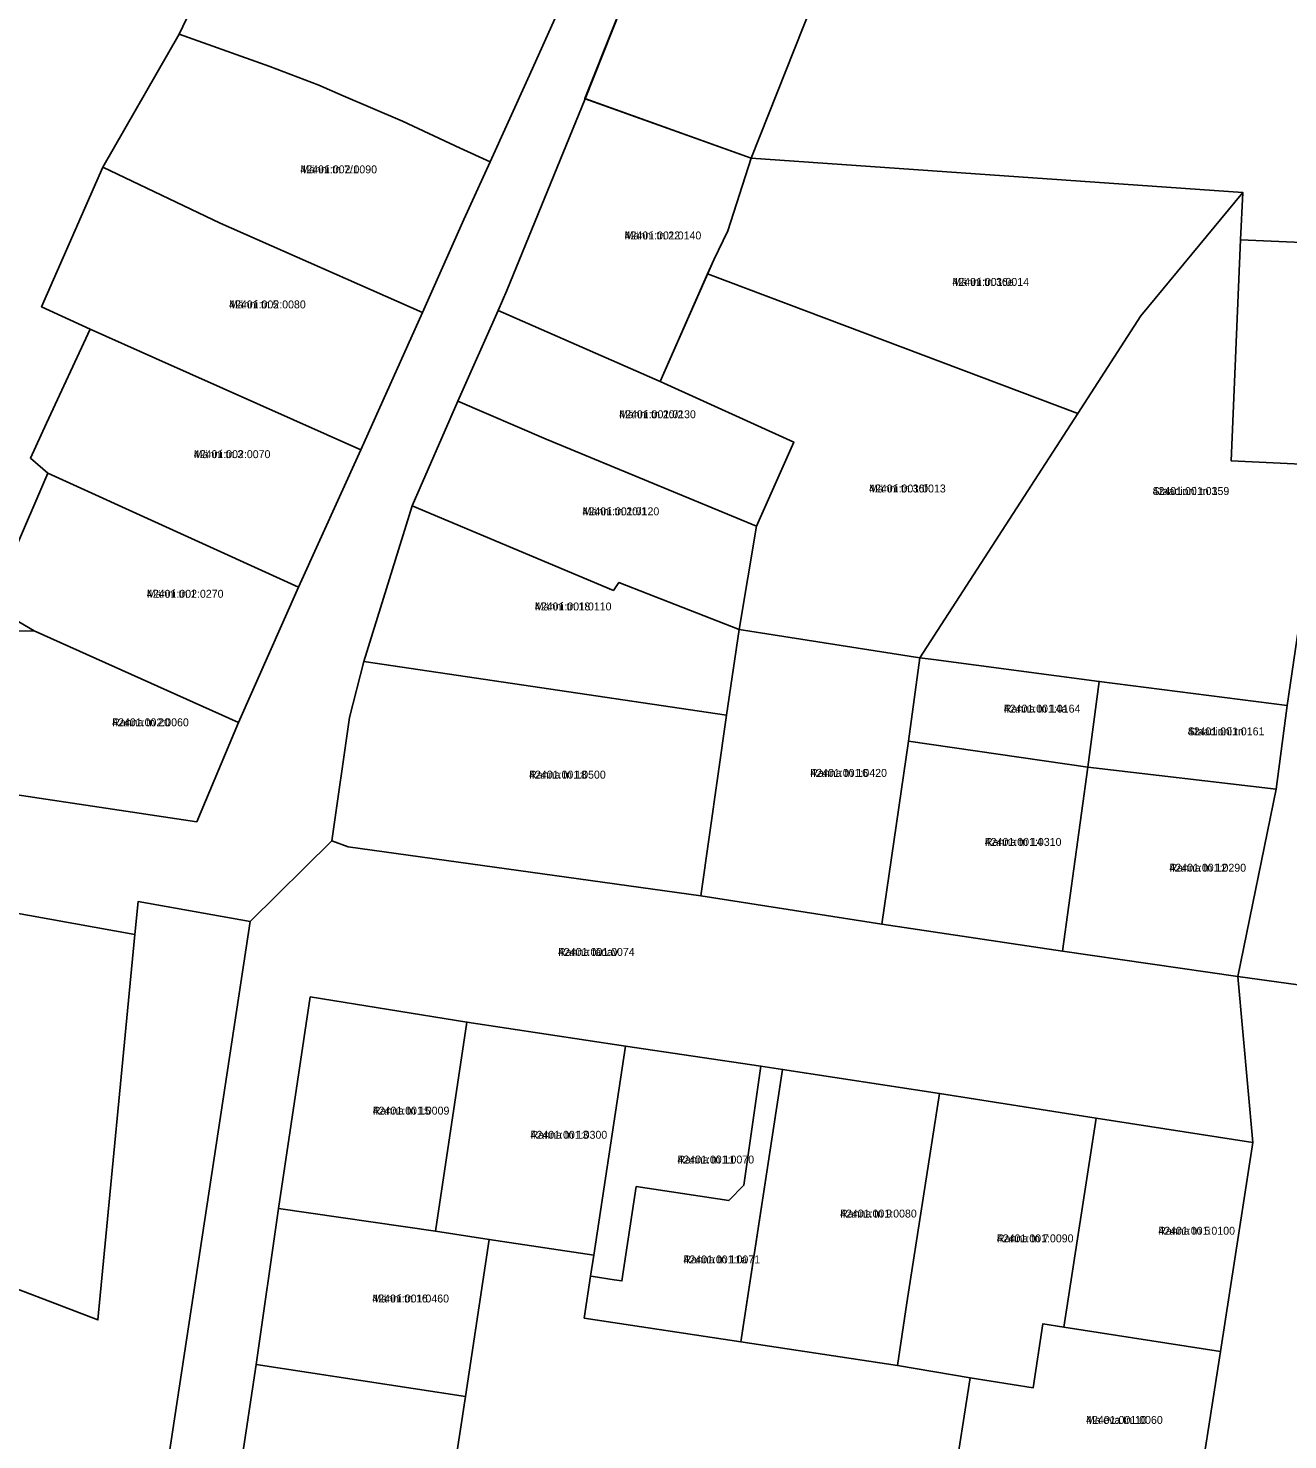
# Model space of a CAD drawing. Extents: x 595979 to 597983, y 6604231 to 6607350.
# Drawn here: x 596786.2 to 597024.3, y 6605469.2 to 6605736 of the extents above; entities that cross this region are included whole.
import ezdxf

# ---------------------------------------------------------------- set-up
doc = ezdxf.new("R2010")
doc.units = 0
for name, color, linetype in [('L_AADRESS', 7, 'Continuous'), ('PIIR', 7, 'Continuous'), ('TUNNUS', 7, 'Continuous')]:
    doc.layers.add(name, color=color, linetype=linetype)

msp = doc.modelspace()

# ---------------------------------------------------------------- linework, layer by layer
at = {"layer": 'PIIR'}
for points in [[(597072.09, 6605693.55), (597015.38, 6605695.99), (597015.83, 6605704.95), (596922.84, 6605711.45), (596939.26, 6605752.73), (596952.71, 6605775.97), (596976.59, 6605810.34), (596999.07, 6605842.72), (597019.57, 6605872.58), (597011.42, 6605878.38), (597008.14, 6605880.65), (596989.77, 6605893.07), (596995.37, 6605898.95), (597000.43, 6605895.48), (597004.6, 6605901.84), (597028.34, 6605885.84)], [(596692.66, 6605778.16), (596685.03, 6605734.09), (596683.77, 6605728.06), (596677.38, 6605692.71), (596670.24, 6605653.13), (596662.9, 6605610.91), (596737.48, 6605597.37), (596777.27, 6605592.09), (596818.04, 6605586.01), (596825.9, 6605604.77), (596837.28, 6605630.34), (596849.07, 6605656.32), (596860.73, 6605682.24), (596868.53, 6605699.81), (596873.49, 6605710.72), (596880.63, 6605726.43), (596886.61, 6605739.74)], [(596908.36, 6605765.26), (596891.49, 6605722.66), (596876.65, 6605686.44), (596875.04, 6605682.66), (596867.38, 6605665.51), (596858.76, 6605645.71), (596849.6, 6605616.3), (596846.89, 6605605.7), (596843.58, 6605582.38), (596828.15, 6605567.17), (596806.93, 6605570.9), (596806.33, 6605564.68), (596747.17, 6605575.34), (596726.8, 6605579.67), (596715.73, 6605560.98), (596707.32, 6605548), (596699.82, 6605552.72), (596718.61, 6605580.89), (596599.67, 6605601.99), (596602.72, 6605622.28), (596653.42, 6605613.98), (596660.98, 6605658.96), (596667.81, 6605698.76), (596674.62, 6605737.93)], [(596804.06, 6605408.95), (596828.15, 6605567.17), (596843.58, 6605582.38), (596846.68, 6605581.28), (596913.35, 6605572), (596947.55, 6605566.65), (596981.77, 6605561.56), (597014.88, 6605556.72), (597017.75, 6605525.39), (596988.11, 6605530), (596958.47, 6605534.61), (596928.82, 6605539.17), (596924.71, 6605539.8), (596899.12, 6605543.59), (596869.12, 6605548.12), (596839.5, 6605552.88), (596833.49, 6605512.87), (596829.27, 6605483.41), (596824.76, 6605453.75)], [(597006.53, 6605453.26), (597011.61, 6605485.87), (597017.75, 6605525.39), (597014.88, 6605556.72), (597046.44, 6605552.43), (597080.35, 6605547.38), (597119.25, 6605542.22), (597133.33, 6605530.05), (597151.91, 6605490.59), (597176.76, 6605502.37), (597175.32, 6605508.24), (597200.25, 6605502.72), (597245.72, 6605496.35), (597249.71, 6605498.34), (597254.66, 6605493.15)], [(596864.31, 6605447.73), (596868.82, 6605477.39), (596873.33, 6605507.05), (596893.1, 6605504.05), (596892.5, 6605500.11), (596891.3, 6605492.19), (596920.89, 6605487.71), (596950.55, 6605483.23), (596964.28, 6605480.86), (596961.09, 6605460.33)]]:
    msp.add_lwpolyline(points, dxfattribs=at)
for points in [[(596783.16, 6605636.35), (596742.46, 6605643.65), (596743.26, 6605663.24), (596743.76, 6605681.63), (596750.48, 6605716.38), (596683.77, 6605728.06), (596685.03, 6605734.09), (596751.3, 6605722.5), (596753.04, 6605730.24), (596756.61, 6605766.92), (596781.4, 6605764.04), (596806.3, 6605761.22), (596821.32, 6605793.9), (596835.19, 6605774.82), (596828.35, 6605763.51), (596814.68, 6605734.88), (596800.26, 6605709.74), (596788.69, 6605683.33), (596797.85, 6605679.12), (596789.61, 6605661.31), (596786.57, 6605654.73), (596789.87, 6605651.91)], [(596908.36, 6605765.26), (596939.26, 6605752.73), (596922.84, 6605711.45), (596891.4, 6605722.68)], [(596828.35, 6605763.51), (596841.88, 6605757.97), (596886.61, 6605739.74), (596880.63, 6605726.43), (596873.49, 6605710.72), (596867.83, 6605713.3), (596856.93, 6605718.44), (596845.7, 6605723.18), (596841.09, 6605725.22), (596831.87, 6605728.75), (596814.68, 6605734.88)], [(596814.68, 6605734.88), (596831.87, 6605728.75), (596841.09, 6605725.22), (596845.7, 6605723.18), (596856.93, 6605718.44), (596867.83, 6605713.3), (596873.49, 6605710.72), (596868.53, 6605699.81), (596860.73, 6605682.24), (596822.43, 6605699.15), (596800.26, 6605709.74)], [(596891.49, 6605722.66), (596922.84, 6605711.45), (596918.48, 6605697.68), (596915.78, 6605692.24), (596905.65, 6605669.19), (596875.04, 6605682.66), (596876.65, 6605686.44)], [(596800.26, 6605709.74), (596822.43, 6605699.15), (596860.73, 6605682.24), (596849.07, 6605656.32), (596810.29, 6605673.57), (596797.85, 6605679.12), (596788.69, 6605683.33)], [(596922.84, 6605711.45), (597015.83, 6605704.95), (596996.56, 6605681.6), (596984.67, 6605663.14), (596914.6, 6605689.55), (596915.78, 6605692.24), (596918.48, 6605697.68)], [(596996.56, 6605681.6), (597015.83, 6605704.95), (597015.38, 6605695.99), (597013.65, 6605654.21), (597042.81, 6605652.85), (597042.02, 6605646.89), (597030, 6605647.37), (597024.26, 6605607.99), (596988.68, 6605612.52), (596957.38, 6605616.65), (596954.75, 6605616.95), (596984.67, 6605663.14)], [(597013.65, 6605654.21), (597015.38, 6605695.99), (597072.09, 6605693.55), (597070.41, 6605657.66), (597061.85, 6605657.99), (597053.54, 6605601.01), (597051.38, 6605586.37), (597046.44, 6605552.43), (597014.88, 6605556.72), (597022.14, 6605592.15), (597024.26, 6605607.99), (597030, 6605647.37), (597042.02, 6605646.89), (597042.81, 6605652.85)], [(596914.6, 6605689.55), (596984.67, 6605663.14), (596954.75, 6605616.95), (596920.58, 6605622.32), (596923.87, 6605641.88), (596930.92, 6605657.76), (596905.65, 6605669.19)], [(596875.04, 6605682.66), (596905.65, 6605669.19), (596930.92, 6605657.76), (596923.87, 6605641.88), (596884.08, 6605658.29), (596867.38, 6605665.51)], [(596797.85, 6605679.12), (596810.29, 6605673.57), (596849.07, 6605656.32), (596837.28, 6605630.34), (596789.87, 6605651.91), (596786.57, 6605654.73), (596789.61, 6605661.31)], [(596867.38, 6605665.51), (596884.08, 6605658.29), (596923.87, 6605641.88), (596920.58, 6605622.32), (596903.3, 6605629.06), (596897.85, 6605631.23), (596896.82, 6605629.73), (596858.76, 6605645.71)], [(596789.87, 6605651.91), (596837.28, 6605630.34), (596825.9, 6605604.77), (596787.26, 6605622.06), (596781.18, 6605625.67), (596780.49, 6605625.75), (596781.17, 6605631.75), (596783.16, 6605636.35)], [(596858.76, 6605645.71), (596896.82, 6605629.73), (596897.85, 6605631.23), (596903.3, 6605629.06), (596920.58, 6605622.32), (596918.2, 6605606.16), (596849.6, 6605616.3)], [(596787.26, 6605622.06), (596825.9, 6605604.77), (596818.04, 6605586.01), (596777.27, 6605592.09), (596780.26, 6605622.05)], [(596920.58, 6605622.32), (596954.75, 6605616.95), (596952.6, 6605601.21), (596947.55, 6605566.65), (596913.35, 6605572), (596918.2, 6605606.16)], [(596849.6, 6605616.3), (596918.2, 6605606.16), (596913.35, 6605572), (596846.68, 6605581.28), (596843.58, 6605582.38), (596846.89, 6605605.7)], [(596952.6, 6605601.21), (596954.75, 6605616.95), (596957.38, 6605616.65), (596988.68, 6605612.52), (596986.56, 6605596.32)], [(596986.56, 6605596.32), (596988.68, 6605612.52), (597024.26, 6605607.99), (597022.14, 6605592.15)], [(596986.56, 6605596.32), (596981.77, 6605561.56), (596947.55, 6605566.65), (596952.6, 6605601.21)], [(597022.14, 6605592.15), (597014.88, 6605556.72), (596981.77, 6605561.56), (596986.56, 6605596.32)], [(596747.17, 6605575.34), (596806.33, 6605564.68), (596799.33, 6605491.84), (596785.62, 6605497.09), (596736.33, 6605515.61), (596740.22, 6605537.04)], [(596707.32, 6605548), (596720.74, 6605540.34), (596740.22, 6605537.04), (596736.33, 6605515.61), (596785.62, 6605497.09), (596799.33, 6605491.84), (596806.33, 6605564.68), (596806.93, 6605570.9), (596828.15, 6605567.17), (596804.06, 6605408.95), (596636.26, 6605434.88), (596646.27, 6605453.64), (596655.33, 6605467.74), (596693.66, 6605524.62)], [(596839.5, 6605552.88), (596869.12, 6605548.12), (596863.18, 6605508.59), (596833.49, 6605512.87)], [(596899.12, 6605543.59), (596893.1, 6605504.05), (596873.33, 6605507.05), (596863.18, 6605508.59), (596869.12, 6605548.12)], [(596924.71, 6605539.8), (596921.51, 6605517.28), (596918.67, 6605514.4), (596901.15, 6605517.03), (596898.43, 6605499.2), (596896.95, 6605499.41), (596892.99, 6605500.03), (596892.5, 6605500.11), (596893.1, 6605504.05), (596899.12, 6605543.59)], [(596892.5, 6605500.11), (596892.99, 6605500.03), (596896.95, 6605499.41), (596898.43, 6605499.2), (596901.15, 6605517.03), (596918.67, 6605514.4), (596921.51, 6605517.28), (596924.71, 6605539.8), (596928.82, 6605539.17), (596920.89, 6605487.71), (596891.3, 6605492.19)], [(596922.74, 6605499.64), (596928.82, 6605539.17), (596958.47, 6605534.61), (596952.32, 6605495.08), (596950.55, 6605483.23), (596920.89, 6605487.71)], [(596988.11, 6605530), (596981.97, 6605490.48), (596978.02, 6605491.09), (596976.2, 6605479.01), (596964.28, 6605480.86), (596950.55, 6605483.23), (596952.32, 6605495.08), (596958.47, 6605534.61)], [(597017.75, 6605525.39), (597011.61, 6605485.87), (596981.97, 6605490.48), (596988.11, 6605530)], [(596863.18, 6605508.59), (596873.33, 6605507.05), (596868.82, 6605477.39), (596829.27, 6605483.41), (596833.49, 6605512.87)], [(596981.97, 6605490.48), (597011.61, 6605485.87), (597006.53, 6605453.26), (596961.09, 6605460.33), (596964.28, 6605480.86), (596976.2, 6605479.01), (596978.02, 6605491.09)], [(596868.82, 6605477.39), (596864.31, 6605447.73), (596824.76, 6605453.75), (596829.27, 6605483.41)]]:
    msp.add_lwpolyline(points, close=True, dxfattribs=at)

# ---------------------------------------------------------------- texts
at = {"layer": 'L_AADRESS'}
for s, p in [('Männi tn 7/1', (596837.62, 6605708.56)), ('Männi tn 22', (596898.94, 6605696.07)), ('Männi tn 36e', (596960.92, 6605687.29)), ('Männi tn 5', (596824.14, 6605683.03)), ('Männi tn 20/2', (596897.91, 6605662.27)), ('Männi tn 3', (596817.46, 6605654.73)), ('Männi tn 36f', (596945.16, 6605648.24)), ('Staadioni tn 3', (596998.78, 6605647.76)), ('Männi tn 20/1', (596890.99, 6605643.92)), ('Männi tn 1', (596808.59, 6605628.34)), ('Männi tn 18', (596881.96, 6605625.94)), ('Ranna tn 14a', (596970.63, 6605606.63)), ('Ranna tn 20', (596802.03, 6605604.04)), ('Staadioni tn 1', (597005.43, 6605602.33)), ('Ranna tn 18', (596880.87, 6605594.15)), ('Ranna tn 16', (596934.05, 6605594.48)), ('Ranna tn 14', (596967.05, 6605581.44)), ('Ranna tn 12', (597001.96, 6605576.56)), ('Ranna tänav', (596886.34, 6605560.64)), ('Ranna tn 15', (596851.3, 6605530.64)), ('Ranna tn 13', (596881.15, 6605526.08)), ('Ranna tn 11', (596908.92, 6605521.4)), ('Ranna tn 9', (596939.68, 6605511.19)), ('Ranna tn 5', (596999.86, 6605507.94)), ('Ranna tn 7', (596969.33, 6605506.5)), ('Ranna tn 11a', (596910.06, 6605502.52)), ('Männi tn 16', (596851.23, 6605495.13)), ('Maleva tn 10', (596986.2, 6605472.18))]:
    msp.add_text(s, height=1.5, dxfattribs=at).set_placement(p)
at = {"layer": 'TUNNUS'}
for s, p in [('42401:002:0090', (596837.62, 6605708.56)), ('42401:001:0140', (596898.94, 6605696.07)), ('42401:001:0014', (596960.92, 6605687.29)), ('42401:002:0080', (596824.14, 6605683.03)), ('42401:001:0130', (596897.91, 6605662.27)), ('42401:002:0070', (596817.46, 6605654.73)), ('42401:001:0013', (596945.16, 6605648.24)), ('42401:001:0159', (596998.78, 6605647.76)), ('42401:001:0120', (596890.99, 6605643.92)), ('42401:002:0270', (596808.59, 6605628.34)), ('42401:001:0110', (596881.96, 6605625.94)), ('42401:001:0164', (596970.63, 6605606.63)), ('42401:002:0060', (596802.03, 6605604.04)), ('42401:001:0161', (597005.43, 6605602.33)), ('42401:001:0500', (596880.87, 6605594.15)), ('42401:001:0420', (596934.05, 6605594.48)), ('42401:001:0310', (596967.05, 6605581.44)), ('42401:001:0290', (597001.96, 6605576.56)), ('42401:001:0074', (596886.34, 6605560.64)), ('42401:001:0009', (596851.3, 6605530.64)), ('42401:001:0300', (596881.15, 6605526.08)), ('42401:001:0070', (596908.92, 6605521.4)), ('42401:001:0080', (596939.68, 6605511.19)), ('42401:001:0100', (596999.86, 6605507.94)), ('42401:001:0090', (596969.33, 6605506.5)), ('42401:001:0071', (596910.06, 6605502.52)), ('42401:001:0460', (596851.23, 6605495.13)), ('42401:001:0060', (596986.2, 6605472.18))]:
    msp.add_text(s, height=1.5, dxfattribs=at).set_placement(p)

doc.saveas('drawing.dxf')
